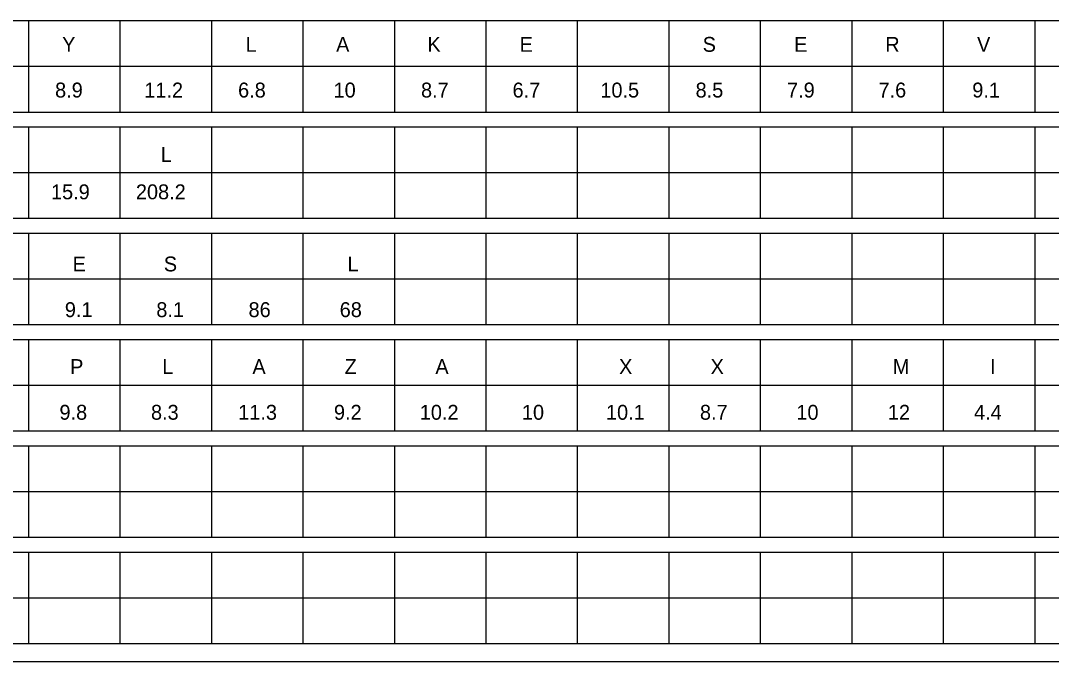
# Model space of a CAD drawing. Extents: x 17890071 to 17890754, y 17897628 to 17897992.
# Drawn here: x 17890099.93 to 17890133.85, y 17897822.61 to 17897843.68 of the extents above; entities that cross this region are included whole.
import ezdxf

# ---------------------------------------------------------------- set-up
doc = ezdxf.new("R2010")
doc.units = 0
doc.layers.add('GSSign', color=7, linetype='Continuous')
doc.layers.add('SheetLinesMisc2_dp', color=7, linetype='Continuous')

msp = doc.modelspace()

# ---------------------------------------------------------------- linework, layer by layer
at = {"layer": 'SheetLinesMisc2_dp'}
for p, q in [((17890077.364, 17897843.684), (17890151.359, 17897843.684)), ((17890100.188, 17897843.684), (17890100.188, 17897840.678)), ((17890103.198, 17897843.684), (17890103.198, 17897840.678)), ((17890106.208, 17897843.684), (17890106.208, 17897840.678)), ((17890109.218, 17897843.684), (17890109.218, 17897840.678)), ((17890112.228, 17897843.684), (17890112.228, 17897840.678)), ((17890115.238, 17897843.684), (17890115.238, 17897840.678)), ((17890118.248, 17897843.684), (17890118.248, 17897840.678)), ((17890121.258, 17897843.684), (17890121.258, 17897840.678)), ((17890124.269, 17897843.684), (17890124.269, 17897840.678)), ((17890127.279, 17897843.684), (17890127.279, 17897840.678)), ((17890130.289, 17897843.684), (17890130.289, 17897840.678)), ((17890133.299, 17897843.684), (17890133.299, 17897840.678)), ((17890077.364, 17897842.181), (17890151.359, 17897842.181)), ((17890077.364, 17897840.678), (17890151.359, 17897840.678)), ((17890077.364, 17897840.188), (17890151.359, 17897840.188)), ((17890100.188, 17897840.188), (17890100.188, 17897837.182)), ((17890103.198, 17897840.188), (17890103.198, 17897837.182)), ((17890106.208, 17897840.188), (17890106.208, 17897837.182)), ((17890109.218, 17897840.188), (17890109.218, 17897837.182)), ((17890112.228, 17897840.188), (17890112.228, 17897837.182)), ((17890115.238, 17897840.188), (17890115.238, 17897837.182)), ((17890118.248, 17897840.188), (17890118.248, 17897837.182)), ((17890121.258, 17897840.188), (17890121.258, 17897837.182)), ((17890124.269, 17897840.188), (17890124.269, 17897837.182)), ((17890127.279, 17897840.188), (17890127.279, 17897837.182)), ((17890130.289, 17897840.188), (17890130.289, 17897837.182)), ((17890133.299, 17897840.188), (17890133.299, 17897837.182)), ((17890077.364, 17897838.684), (17890151.359, 17897838.685)), ((17890077.364, 17897837.182), (17890151.359, 17897837.182)), ((17890077.364, 17897836.692), (17890151.359, 17897836.692)), ((17890100.188, 17897836.692), (17890100.188, 17897833.686)), ((17890103.198, 17897836.692), (17890103.198, 17897833.686)), ((17890106.208, 17897836.692), (17890106.208, 17897833.686)), ((17890109.218, 17897836.692), (17890109.218, 17897833.686)), ((17890112.228, 17897836.692), (17890112.228, 17897833.686)), ((17890115.238, 17897836.692), (17890115.238, 17897833.686)), ((17890118.248, 17897836.692), (17890118.248, 17897833.686)), ((17890121.258, 17897836.692), (17890121.258, 17897833.686)), ((17890124.269, 17897836.692), (17890124.269, 17897833.686)), ((17890127.279, 17897836.692), (17890127.279, 17897833.686)), ((17890130.289, 17897836.692), (17890130.289, 17897833.686)), ((17890133.299, 17897836.692), (17890133.299, 17897833.686)), ((17890077.364, 17897835.188), (17890151.359, 17897835.188)), ((17890077.364, 17897833.686), (17890151.359, 17897833.686)), ((17890077.364, 17897833.195), (17890151.359, 17897833.195)), ((17890100.188, 17897833.195), (17890100.188, 17897830.189)), ((17890103.198, 17897833.195), (17890103.198, 17897830.189)), ((17890106.208, 17897833.195), (17890106.208, 17897830.189)), ((17890109.218, 17897833.195), (17890109.218, 17897830.189)), ((17890112.228, 17897833.195), (17890112.228, 17897830.189)), ((17890115.238, 17897833.195), (17890115.238, 17897830.189)), ((17890118.248, 17897833.195), (17890118.248, 17897830.189)), ((17890121.258, 17897833.195), (17890121.258, 17897830.189)), ((17890124.269, 17897833.195), (17890124.269, 17897830.189)), ((17890127.279, 17897833.195), (17890127.279, 17897830.189)), ((17890130.289, 17897833.195), (17890130.289, 17897830.189)), ((17890133.299, 17897833.195), (17890133.299, 17897830.189)), ((17890077.364, 17897831.692), (17890151.359, 17897831.692)), ((17890077.364, 17897830.189), (17890151.359, 17897830.189)), ((17890077.364, 17897829.699), (17890151.359, 17897829.699)), ((17890100.188, 17897829.699), (17890100.188, 17897826.693)), ((17890103.198, 17897829.699), (17890103.198, 17897826.693)), ((17890106.208, 17897829.699), (17890106.208, 17897826.693)), ((17890109.218, 17897829.699), (17890109.218, 17897826.693)), ((17890112.228, 17897829.699), (17890112.228, 17897826.693)), ((17890115.238, 17897829.699), (17890115.238, 17897826.693)), ((17890118.248, 17897829.699), (17890118.248, 17897826.693)), ((17890121.258, 17897829.699), (17890121.258, 17897826.693)), ((17890124.269, 17897829.699), (17890124.269, 17897826.693)), ((17890127.279, 17897829.699), (17890127.279, 17897826.693)), ((17890130.289, 17897829.699), (17890130.289, 17897826.693)), ((17890133.299, 17897829.699), (17890133.299, 17897826.693)), ((17890077.364, 17897828.196), (17890151.359, 17897828.196)), ((17890077.364, 17897826.693), (17890151.359, 17897826.693)), ((17890077.364, 17897826.202), (17890151.359, 17897826.202)), ((17890100.188, 17897826.202), (17890100.188, 17897823.197)), ((17890103.198, 17897826.202), (17890103.198, 17897823.197)), ((17890106.208, 17897826.202), (17890106.208, 17897823.197)), ((17890109.218, 17897826.202), (17890109.218, 17897823.197)), ((17890112.228, 17897826.202), (17890112.228, 17897823.197)), ((17890115.238, 17897826.202), (17890115.238, 17897823.197)), ((17890118.248, 17897826.202), (17890118.248, 17897823.197)), ((17890121.258, 17897826.202), (17890121.258, 17897823.197)), ((17890124.269, 17897826.202), (17890124.269, 17897823.197)), ((17890127.279, 17897826.202), (17890127.279, 17897823.197)), ((17890130.289, 17897826.202), (17890130.289, 17897823.197)), ((17890133.299, 17897826.202), (17890133.299, 17897823.197)), ((17890077.364, 17897824.7), (17890151.359, 17897824.7)), ((17890077.364, 17897823.197), (17890151.359, 17897823.197)), ((17890076.643, 17897822.606), (17890151.871, 17897822.606))]:
    msp.add_line(p, q, dxfattribs=at)

# ---------------------------------------------------------------- texts
at = {"layer": 'GSSign'}
for s, height, p in [('Y', 0.49, (17890101.298, 17897842.658)), ('L', 0.49, (17890107.335, 17897842.658)), ('A', 0.49, (17890110.312, 17897842.658)), ('K', 0.49, (17890113.317, 17897842.658)), ('E', 0.49, (17890116.351, 17897842.658)), ('S', 0.49, (17890122.373, 17897842.658)), ('E', 0.49, (17890125.382, 17897842.658)), ('R', 0.49, (17890128.381, 17897842.658)), ('V', 0.49, (17890131.401, 17897842.658)), ('8.9', 0.4902, (17890101.066, 17897841.155)), ('11.2', 0.4902, (17890104.001, 17897841.155)), ('6.8', 0.4902, (17890107.087, 17897841.155)), ('10', 0.4902, (17890110.228, 17897841.155)), ('8.7', 0.4902, (17890113.106, 17897841.155)), ('6.7', 0.4902, (17890116.117, 17897841.155)), ('10.5', 0.4902, (17890119.006, 17897841.155)), ('8.5', 0.4902, (17890122.14, 17897841.155)), ('7.9', 0.4902, (17890125.149, 17897841.155)), ('7.6', 0.4902, (17890128.158, 17897841.155)), ('9.1', 0.4902, (17890131.244, 17897841.155)), ('L', 0.49, (17890104.542, 17897839.036)), ('15.9', 0.4902, (17890100.931, 17897837.807)), ('208.2', 0.4902, (17890103.724, 17897837.807)), ('E', 0.49, (17890101.644, 17897835.434)), ('S', 0.49, (17890104.643, 17897835.434)), ('L', 0.49, (17890110.687, 17897835.434)), ('9.1', 0.4902, (17890101.387, 17897833.931)), ('8.1', 0.4902, (17890104.397, 17897833.931)), ('86', 0.4902, (17890107.431, 17897833.931)), ('68', 0.4902, (17890110.43, 17897833.931)), ('P', 0.49, (17890101.56, 17897832.058)), ('L', 0.49, (17890104.594, 17897832.058)), ('A', 0.49, (17890107.558, 17897832.058)), ('Z', 0.49, (17890110.591, 17897832.058)), ('A', 0.49, (17890113.578, 17897832.058)), ('X', 0.49, (17890119.622, 17897832.058)), ('X', 0.49, (17890122.633, 17897832.058)), ('M', 0.49, (17890128.63, 17897832.058)), ('I', 0.49, (17890131.827, 17897832.058)), ('9.8', 0.4902, (17890101.21, 17897830.555)), ('8.3', 0.4902, (17890104.221, 17897830.555)), ('11.3', 0.4902, (17890107.091, 17897830.555)), ('9.2', 0.4902, (17890110.241, 17897830.555)), ('10.2', 0.4902, (17890113.065, 17897830.555)), ('10', 0.4902, (17890116.425, 17897830.555)), ('10.1', 0.4902, (17890119.191, 17897830.555)), ('8.7', 0.4902, (17890122.283, 17897830.555)), ('10', 0.4902, (17890125.456, 17897830.555)), ('12', 0.4902, (17890128.467, 17897830.555)), ('4.4', 0.4902, (17890131.302, 17897830.555))]:
    msp.add_text(s, height=height, dxfattribs=at).set_placement(p)

doc.saveas('drawing.dxf')
